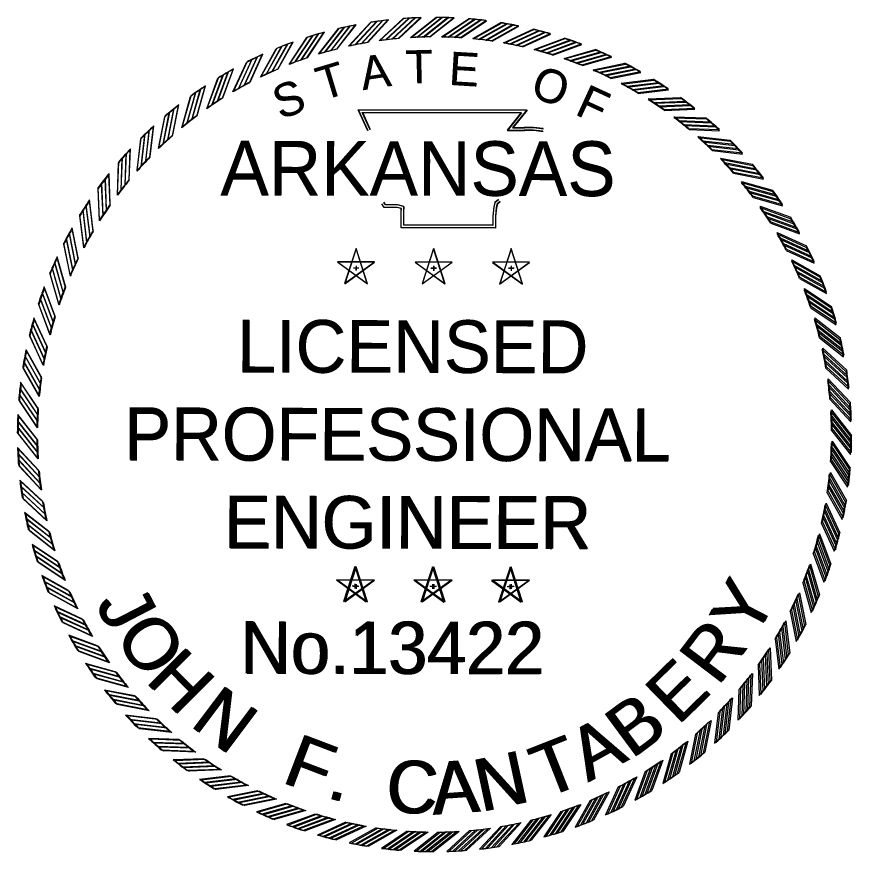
# Model space of a CAD drawing. Extents: x 0 to 38.1, y -1.4 to 22.
# Drawn here: x 35.582 to 38.013, y 15.407 to 17.836 of the extents above; entities that cross this region are included whole.
import ezdxf

# ---------------------------------------------------------------- set-up
doc = ezdxf.new("R2010")
doc.units = 0
doc.layers.add('Default', color=7, linetype='Continuous')

# ---------------------------------------------------------------- blocks, each defined once
blk = doc.blocks.new('STAR')
at = {"layer": 'Default'}
for p, q in [((-0.0001, 0.0615), (-0.0366, -0.0504)), ((0.0362, -0.0503), (0, 0.0617)), ((0.0587, 0.0188), (-0.059, 0.0189)), ((-0.0589, 0.0188), (0.0363, -0.0505)), ((-0.0365, -0.0503), (0.0589, 0.0188)), ((-0.0085, 0), (0.009, 0)), ((0, 0.0063), (0, -0.0085))]:
    blk.add_line(p, q, dxfattribs=at)
blk = doc.blocks.new('RP')
at = {"layer": 'Default'}
for p, q in [((-0.0781, 1.2656), (0.003, 1.33)), ((-0.058, 1.2667), (0.0216, 1.3299)), ((-0.0375, 1.2674), (0.0405, 1.3294)), ((-0.0176, 1.2679), (0.059, 1.3287))]:
    blk.add_line(p, q, dxfattribs=at)
for radius, start, end in [(1.33, 87.4562, 89.8699), (1.268, 90.7933, 93.5307)]:
    blk.add_arc((0, 0), radius, start, end, dxfattribs=at)

msp = doc.modelspace()

# ---------------------------------------------------------------- linework, layer by layer
at = {"layer": 'Default'}
for points in [[(36.6042, 17.5043), (36.5758, 17.5657), (37.0662, 17.566), (37.0253, 17.5145), (37.0586, 17.5149), (37.0864, 17.5153), (37.1142, 17.5122)], [(36.6051, 17.5046), (36.577, 17.5661), (37.0674, 17.5647), (37.0263, 17.5134), (37.0596, 17.5137), (37.0874, 17.514), (37.1152, 17.5108)], [(36.6112, 17.5076), (36.588, 17.5579), (37.0501, 17.5582), (37.009, 17.5065), (37.0587, 17.5071), (37.086, 17.5075), (37.1134, 17.5045)], [(36.6122, 17.5079), (36.5891, 17.5583), (37.0513, 17.557), (37.01, 17.5055), (37.0597, 17.5059), (37.087, 17.5062), (37.1143, 17.5031)], [(36.989, 17.2988), (36.9806, 17.292), (36.9778, 17.2818), (36.9751, 17.2564), (36.9751, 17.2225), (36.7013, 17.2225), (36.7013, 17.2682), (36.7013, 17.2784), (36.6902, 17.2818), (36.6512, 17.2818), (36.6443, 17.2924)], [(36.9892, 17.2978), (36.9808, 17.291), (36.978, 17.2809), (36.9752, 17.2554), (36.9751, 17.2215), (36.7013, 17.2225), (36.7014, 17.2682), (36.7015, 17.2784), (36.6904, 17.2818), (36.6514, 17.282), (36.6446, 17.2926)], [(36.9841, 17.3048), (36.9738, 17.2964), (36.9702, 17.2833), (36.9673, 17.2568), (36.9673, 17.2303), (36.7091, 17.2303), (36.7091, 17.2682), (36.7091, 17.2842), (36.6913, 17.2896), (36.6554, 17.2896), (36.6508, 17.2966)], [(36.9843, 17.3038), (36.974, 17.2955), (36.9704, 17.2823), (36.9674, 17.2559), (36.9673, 17.2293), (36.7091, 17.2302), (36.7092, 17.2682), (36.7093, 17.2841), (36.6916, 17.2896), (36.6557, 17.2897), (36.6511, 17.2968)]]:
    msp.add_lwpolyline(points, dxfattribs=at)

# ---------------------------------------------------------------- block references
for name, p, xscale, yscale, rotation in [('RP', (36.799, 16.6219), 0.9117655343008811, 0.9117655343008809, 9.000000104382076), ('RP', (36.7969, 16.6215), 0.9117655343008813, 0.9117655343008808, 8.804199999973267), ('RP', (36.799, 16.6219), 0.9117655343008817, 0.9117655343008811, 4.500000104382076), ('RP', (36.7969, 16.6215), 0.9117655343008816, 0.9117655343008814, 4.304199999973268), ('RP', (36.799, 16.6219), 0.9117655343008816, 0.911765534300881, 1.0438208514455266e-07), ('RP', (36.7969, 16.6215), 0.9117655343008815, 0.911765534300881, -0.19580000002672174), ('RP', (36.799, 16.6219), 0.9117655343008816, 0.911765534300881, -4.499999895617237), ('RP', (36.7969, 16.6215), 0.9117655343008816, 0.9117655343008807, -4.695800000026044), ('RP', (36.799, 16.6219), 0.9117655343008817, 0.9117655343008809, -8.999999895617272), ('RP', (36.7969, 16.6215), 0.9117655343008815, 0.911765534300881, -9.195800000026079), ('RP', (36.799, 16.6219), 0.9117655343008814, 0.9117655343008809, 13.500000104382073), ('RP', (36.7969, 16.6215), 0.9117655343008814, 0.9117655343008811, 13.304199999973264), ('RP', (36.799, 16.6219), 0.9117655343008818, 0.9117655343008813, -13.499999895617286), ('RP', (36.7969, 16.6215), 0.9117655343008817, 0.9117655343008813, -13.695800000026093), ('RP', (36.799, 16.6219), 0.9117655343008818, 0.911765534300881, -17.99999989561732), ('RP', (36.7969, 16.6215), 0.9117655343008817, 0.911765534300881, -18.19580000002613), ('RP', (36.799, 16.6219), 0.9117655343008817, 0.9117655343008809, 18.000000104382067), ('RP', (36.7969, 16.6215), 0.9117655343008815, 0.9117655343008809, 17.80419999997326), ('RP', (36.799, 16.6219), 0.9117655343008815, 0.911765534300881, 22.500000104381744), ('RP', (36.7969, 16.6215), 0.9117655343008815, 0.911765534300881, 22.304199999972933), ('RP', (36.799, 16.6219), 0.9117655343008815, 0.9117655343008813, -22.499999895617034), ('RP', (36.7969, 16.6215), 0.9117655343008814, 0.9117655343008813, -22.695800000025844), ('RP', (36.799, 16.6219), 0.9117655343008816, 0.9117655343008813, 27.000000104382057), ('RP', (36.7969, 16.6215), 0.9117655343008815, 0.9117655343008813, 26.80419999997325), ('RP', (36.799, 16.6219), 0.9117655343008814, 0.9117655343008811, -26.999999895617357), ('RP', (36.7969, 16.6215), 0.9117655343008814, 0.911765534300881, -27.19580000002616), ('RP', (36.799, 16.6219), 0.911765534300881, 0.9117655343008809, 31.500000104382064), ('RP', (36.7969, 16.6215), 0.9117655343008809, 0.9117655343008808, 31.30419999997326), ('RP', (36.799, 16.6219), 0.9117655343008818, 0.9117655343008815, -31.49999989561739), ('RP', (36.7969, 16.6215), 0.9117655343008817, 0.9117655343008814, -31.695800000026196), ('RP', (36.799, 16.6219), 0.9117655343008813, 0.911765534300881, 36.000000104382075), ('RP', (36.7969, 16.6215), 0.911765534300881, 0.9117655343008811, 35.804199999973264), ('RP', (36.799, 16.6219), 0.9117655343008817, 0.9117655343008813, -35.999999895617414), ('RP', (36.7969, 16.6215), 0.9117655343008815, 0.9117655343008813, -36.195800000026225), ('RP', (36.799, 16.6219), 0.9117655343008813, 0.911765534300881, 40.50000010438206), ('RP', (36.7969, 16.6215), 0.9117655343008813, 0.911765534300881, 40.30419999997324), ('RP', (36.799, 16.6219), 0.9117655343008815, 0.9117655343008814, -40.49999989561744), ('RP', (36.7969, 16.6215), 0.9117655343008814, 0.9117655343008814, -40.69580000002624), ('RP', (36.799, 16.6219), 0.9117655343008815, 0.911765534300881, -44.99999989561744), ('RP', (36.799, 16.6219), 0.9117655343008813, 0.9117655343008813, 45.00000010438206), ('RP', (36.7969, 16.6215), 0.9117655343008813, 0.911765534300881, 44.80419999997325), ('RP', (36.7969, 16.6215), 0.9117655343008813, 0.911765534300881, -45.19580000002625), ('RP', (36.799, 16.6219), 0.911765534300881, 0.9117655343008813, -49.499999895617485), ('RP', (36.7969, 16.6215), 0.911765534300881, 0.911765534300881, -49.69580000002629), ('RP', (36.799, 16.6219), 0.9117655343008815, 0.9117655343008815, 49.500000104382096), ('RP', (36.7969, 16.6215), 0.9117655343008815, 0.9117655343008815, 49.30419999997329), ('RP', (36.799, 16.6219), 0.9117655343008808, 0.9117655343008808, -53.999999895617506), ('RP', (36.7969, 16.6215), 0.9117655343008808, 0.9117655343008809, -54.1958000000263), ('RP', (36.799, 16.6219), 0.9117655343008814, 0.9117655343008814, 54.00000010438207), ('RP', (36.7969, 16.6215), 0.9117655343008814, 0.9117655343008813, 53.804199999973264), ('RP', (36.799, 16.6219), 0.911765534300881, 0.9117655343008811, -58.49999989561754), ('RP', (36.7969, 16.6215), 0.9117655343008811, 0.9117655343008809, -58.695800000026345), ('RP', (36.7969, 16.6215), 0.9117655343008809, 0.9117655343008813, 58.304199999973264), ('RP', (36.799, 16.6219), 0.911765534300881, 0.9117655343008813, 58.50000010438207), ('RP', (36.7969, 16.6215), 0.9117655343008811, 0.9117655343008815, 62.804199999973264), ('RP', (36.799, 16.6219), 0.9117655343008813, 0.9117655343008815, 63.000000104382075), ('RP', (36.7969, 16.6215), 0.9117655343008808, 0.9117655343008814, -63.19580000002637), ('RP', (36.799, 16.6219), 0.911765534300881, 0.9117655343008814, -62.99999989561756), ('RP', (36.7969, 16.6215), 0.911765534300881, 0.9117655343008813, 67.30419999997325), ('STAR', (36.5696, 17.1065), 0.9117655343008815, 0.911765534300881, -0.19580000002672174), ('STAR', (36.57, 17.106), 0.9117655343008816, 0.911765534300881, 1.0438208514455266e-07), ('STAR', (36.7952, 17.1057), 0.9117655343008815, 0.911765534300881, -0.19580000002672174), ('STAR', (36.7956, 17.106), 0.9117655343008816, 0.911765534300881, 1.0438208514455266e-07), ('STAR', (37.0207, 17.1049), 0.9117655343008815, 0.911765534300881, -0.19580000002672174), ('STAR', (37.0211, 17.106), 0.9117655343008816, 0.911765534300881, 1.0438208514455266e-07), ('RP', (36.7969, 16.6215), 0.9117655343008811, 0.9117655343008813, -67.69580000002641), ('RP', (36.799, 16.6219), 0.911765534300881, 0.9117655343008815, -67.49999989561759), ('RP', (36.799, 16.6219), 0.911765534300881, 0.9117655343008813, 67.50000010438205), ('RP', (36.7969, 16.6215), 0.9117655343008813, 0.9117655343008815, 71.80419999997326), ('RP', (36.799, 16.6219), 0.9117655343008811, 0.9117655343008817, 72.00000010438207), ('RP', (36.7969, 16.6215), 0.911765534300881, 0.9117655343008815, -72.19580000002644), ('RP', (36.799, 16.6219), 0.9117655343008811, 0.9117655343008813, -71.99999989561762), ('RP', (36.7969, 16.6215), 0.9117655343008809, 0.911765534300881, -76.69580000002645), ('RP', (36.799, 16.6219), 0.9117655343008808, 0.9117655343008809, -76.49999989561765), ('RP', (36.7969, 16.6215), 0.911765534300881, 0.9117655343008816, 76.30419999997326), ('RP', (36.799, 16.6219), 0.9117655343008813, 0.9117655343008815, 76.50000010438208), ('RP', (36.7969, 16.6215), 0.911765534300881, 0.9117655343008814, -81.19580000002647), ('RP', (36.799, 16.6219), 0.9117655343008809, 0.9117655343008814, -80.99999989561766), ('RP', (36.7969, 16.6215), 0.9117655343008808, 0.9117655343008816, 80.80419999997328), ('RP', (36.799, 16.6219), 0.9117655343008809, 0.9117655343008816, 81.0000001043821), ('RP', (36.7969, 16.6215), 0.9117655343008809, 0.9117655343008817, 85.30419999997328), ('RP', (36.7969, 16.6215), 0.9117655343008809, 0.9117655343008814, -85.69580000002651), ('RP', (36.799, 16.6219), 0.9117655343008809, 0.9117655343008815, -85.49999989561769), ('RP', (36.799, 16.6219), 0.9117655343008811, 0.9117655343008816, 85.50000010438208), ('RP', (36.7969, 16.6215), 0.911765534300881, 0.9117655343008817, 89.80419999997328), ('RP', (36.7969, 16.6215), 0.9117655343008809, 0.9117655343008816, -90.19580000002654), ('RP', (36.799, 16.6219), 0.911765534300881, 0.9117655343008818, -89.99999989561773), ('RP', (36.799, 16.6219), 0.9117655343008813, 0.9117655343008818, 90.0000001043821), ('RP', (36.7969, 16.6215), 0.911765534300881, 0.9117655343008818, 94.30419999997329), ('RP', (36.799, 16.6219), 0.9117655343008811, 0.9117655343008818, 94.5000001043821), ('RP', (36.7969, 16.6215), 0.911765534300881, 0.9117655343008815, -94.69580000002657), ('RP', (36.799, 16.6219), 0.9117655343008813, 0.9117655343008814, -94.49999989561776), ('RP', (36.7969, 16.6215), 0.911765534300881, 0.9117655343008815, -99.19580000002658), ('RP', (36.799, 16.6219), 0.9117655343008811, 0.9117655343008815, -98.99999989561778), ('RP', (36.7969, 16.6215), 0.9117655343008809, 0.9117655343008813, 98.8041999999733), ('RP', (36.799, 16.6219), 0.9117655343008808, 0.9117655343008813, 99.0000001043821), ('RP', (36.7969, 16.6215), 0.9117655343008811, 0.9117655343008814, -103.69580000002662), ('RP', (36.799, 16.6219), 0.911765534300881, 0.9117655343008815, -103.49999989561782), ('RP', (36.7969, 16.6215), 0.911765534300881, 0.9117655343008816, 103.30419999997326), ('RP', (36.799, 16.6219), 0.911765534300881, 0.9117655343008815, 103.50000010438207), ('RP', (36.7969, 16.6215), 0.9117655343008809, 0.9117655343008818, 107.80419999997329), ('RP', (36.799, 16.6219), 0.9117655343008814, 0.9117655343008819, 108.0000001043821), ('RP', (36.7969, 16.6215), 0.9117655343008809, 0.9117655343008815, -108.19580000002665), ('RP', (36.799, 16.6219), 0.9117655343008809, 0.9117655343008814, -107.99999989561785), ('RP', (36.7969, 16.6215), 0.9117655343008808, 0.9117655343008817, -112.69580000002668), ('RP', (36.799, 16.6219), 0.9117655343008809, 0.9117655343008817, -112.49999989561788), ('RP', (36.7969, 16.6215), 0.911765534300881, 0.9117655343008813, 112.30419999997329), ('RP', (36.799, 16.6219), 0.9117655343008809, 0.9117655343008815, 112.5000001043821), ('STAR', (36.5665, 16.1817), 0.9117655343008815, 0.911765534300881, -0.19580000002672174), ('STAR', (36.57, 16.1812), 0.9117655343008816, 0.911765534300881, 1.0438208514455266e-07), ('STAR', (36.792, 16.1809), 0.9117655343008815, 0.911765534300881, -0.19580000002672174), ('STAR', (36.7956, 16.1812), 0.9117655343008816, 0.911765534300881, 1.0438208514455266e-07), ('STAR', (37.0176, 16.1801), 0.9117655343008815, 0.911765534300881, -0.19580000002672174), ('STAR', (37.0211, 16.1812), 0.9117655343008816, 0.911765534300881, 1.0438208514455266e-07), ('RP', (36.7969, 16.6215), 0.9117655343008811, 0.9117655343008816, 116.80419999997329), ('RP', (36.799, 16.6219), 0.9117655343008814, 0.9117655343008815, 117.0000001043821), ('RP', (36.7969, 16.6215), 0.9117655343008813, 0.9117655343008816, -117.19580000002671), ('RP', (36.799, 16.6219), 0.9117655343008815, 0.9117655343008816, -116.9999998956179), ('RP', (36.7969, 16.6215), 0.9117655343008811, 0.9117655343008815, -121.69580000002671), ('RP', (36.799, 16.6219), 0.9117655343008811, 0.9117655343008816, -121.4999998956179), ('RP', (36.7969, 16.6215), 0.9117655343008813, 0.9117655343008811, 121.30419999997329), ('RP', (36.799, 16.6219), 0.9117655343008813, 0.9117655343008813, 121.5000001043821), ('RP', (36.7969, 16.6215), 0.9117655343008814, 0.9117655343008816, -126.19580000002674), ('RP', (36.799, 16.6219), 0.9117655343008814, 0.9117655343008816, -125.99999989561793), ('RP', (36.7969, 16.6215), 0.911765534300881, 0.911765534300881, 125.80419999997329), ('RP', (36.799, 16.6219), 0.911765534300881, 0.9117655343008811, 126.00000010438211), ('RP', (36.799, 16.6219), 0.9117655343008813, 0.9117655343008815, -130.49999989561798), ('RP', (36.7969, 16.6215), 0.9117655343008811, 0.9117655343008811, 130.3041999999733), ('RP', (36.799, 16.6219), 0.911765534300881, 0.9117655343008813, 130.50000010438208), ('RP', (36.7969, 16.6215), 0.9117655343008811, 0.9117655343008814, -130.6958000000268), ('RP', (36.7969, 16.6215), 0.9117655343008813, 0.911765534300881, -135.19580000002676), ('RP', (36.799, 16.6219), 0.9117655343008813, 0.9117655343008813, -134.99999989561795), ('RP', (36.7969, 16.6215), 0.9117655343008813, 0.911765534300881, 134.80419999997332), ('RP', (36.799, 16.6219), 0.9117655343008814, 0.9117655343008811, 135.00000010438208), ('RP', (36.7969, 16.6215), 0.9117655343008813, 0.9117655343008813, 139.30419999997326), ('RP', (36.799, 16.6219), 0.9117655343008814, 0.9117655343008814, 139.50000010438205), ('RP', (36.7969, 16.6215), 0.9117655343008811, 0.9117655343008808, -139.69580000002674), ('RP', (36.799, 16.6219), 0.911765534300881, 0.911765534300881, -139.49999989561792), ('RP', (36.799, 16.6219), 0.9117655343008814, 0.9117655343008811, -143.99999989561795), ('RP', (36.7969, 16.6215), 0.9117655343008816, 0.9117655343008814, 143.8041999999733), ('RP', (36.799, 16.6219), 0.9117655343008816, 0.9117655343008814, 144.00000010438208), ('RP', (36.7969, 16.6215), 0.9117655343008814, 0.9117655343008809, -144.19580000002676), ('RP', (36.7969, 16.6215), 0.9117655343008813, 0.9117655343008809, 148.3041999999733), ('RP', (36.799, 16.6219), 0.9117655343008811, 0.9117655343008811, 148.50000010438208), ('RP', (36.7969, 16.6215), 0.9117655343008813, 0.9117655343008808, -148.69580000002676), ('RP', (36.799, 16.6219), 0.911765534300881, 0.911765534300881, -148.49999989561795), ('RP', (36.7969, 16.6215), 0.9117655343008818, 0.9117655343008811, 152.8041999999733), ('RP', (36.799, 16.6219), 0.9117655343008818, 0.9117655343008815, 153.00000010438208), ('RP', (36.7969, 16.6215), 0.9117655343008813, 0.9117655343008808, -153.1958000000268), ('RP', (36.799, 16.6219), 0.9117655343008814, 0.9117655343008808, -152.99999989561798), ('RP', (36.799, 16.6219), 0.9117655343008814, 0.9117655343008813, -157.4999998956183), ('RP', (36.7969, 16.6215), 0.9117655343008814, 0.9117655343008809, 157.3041999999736), ('RP', (36.799, 16.6219), 0.9117655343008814, 0.911765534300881, 157.50000010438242), ('RP', (36.7969, 16.6215), 0.9117655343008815, 0.9117655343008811, -157.6958000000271), ('RP', (36.7969, 16.6215), 0.9117655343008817, 0.911765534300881, 161.8041999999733), ('RP', (36.799, 16.6219), 0.9117655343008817, 0.9117655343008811, 162.00000010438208), ('RP', (36.7969, 16.6215), 0.9117655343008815, 0.9117655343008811, -162.19580000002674), ('RP', (36.799, 16.6219), 0.9117655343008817, 0.911765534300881, -161.99999989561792), ('RP', (36.7969, 16.6215), 0.9117655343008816, 0.9117655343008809, 166.3041999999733), ('RP', (36.799, 16.6219), 0.9117655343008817, 0.9117655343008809, 166.50000010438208), ('RP', (36.7969, 16.6215), 0.9117655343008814, 0.9117655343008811, -166.69580000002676), ('RP', (36.799, 16.6219), 0.9117655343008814, 0.9117655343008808, -166.49999989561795), ('RP', (36.7969, 16.6215), 0.9117655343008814, 0.9117655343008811, 170.8041999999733), ('RP', (36.799, 16.6219), 0.9117655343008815, 0.911765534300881, 171.00000010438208), ('RP', (36.7969, 16.6215), 0.911765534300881, 0.911765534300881, -171.19580000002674), ('RP', (36.799, 16.6219), 0.9117655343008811, 0.9117655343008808, -170.99999989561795), ('RP', (36.7969, 16.6215), 0.9117655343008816, 0.911765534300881, 175.3041999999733), ('RP', (36.799, 16.6219), 0.9117655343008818, 0.911765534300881, 175.50000010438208), ('RP', (36.7969, 16.6215), 0.9117655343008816, 0.9117655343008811, 179.8041999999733), ('RP', (36.799, 16.6219), 0.9117655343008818, 0.9117655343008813, -179.99999989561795), ('RP', (36.7969, 16.6215), 0.9117655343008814, 0.911765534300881, -175.69580000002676), ('RP', (36.799, 16.6219), 0.9117655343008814, 0.9117655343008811, -175.49999989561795)]:
    msp.add_blockref(name, p, dxfattribs=dict(at, xscale=xscale, yscale=yscale, rotation=rotation))

# ---------------------------------------------------------------- texts
for s, height, rotation, p in [('A', 0.0967, 8.6788, (36.5892, 17.6224)), ('A', 0.0967, 8.483, (36.5906, 17.6227)), ('T', 0.0967, 1.4789, (36.7142, 17.6416)), ('T', 0.0967, 1.2831, (36.7156, 17.6416)), ('E', 0.0967, 356.672, (36.838, 17.6387)), ('E', 0.0967, 356.4762, (36.8394, 17.6382)), ('T', 0.0967, 16.9015, (36.4718, 17.5917)), ('T', 0.0967, 16.7057, (36.473, 17.5925)), ('O', 0.0967, 341.2218, (37.0728, 17.6055)), ('O', 0.0967, 341.026, (37.0741, 17.6042)), ('S', 0.0967, 19.5768, (36.3498, 17.5377)), ('S', 0.0967, 19.7726, (36.3488, 17.5365)), ('F', 0.0967, 335.3628, (37.2032, 17.5545)), ('F', 0.0967, 335.167, (37.2044, 17.5528)), ('ARKANSAS', 0.15788, 0, (36.1749, 17.3164)), ('ARKANSAS', 0.15788, 359.8042, (36.1753, 17.3182)), ('LICENSED', 0.15285, 359.8042, (36.2225, 16.8027)), ('LICENSED', 0.15285, 0, (36.224, 16.8011)), ('PROFESSIONAL', 0.152848, 359.8042, (35.8941, 16.5482)), ('PROFESSIONAL', 0.152848, 0, (35.8964, 16.5454)), ('ENGINEER', 0.15285, 359.8042, (36.1844, 16.2916)), ('ENGINEER', 0.15285, 0, (36.1876, 16.2898)), ('Y', 0.1528, 62.5392, (37.7287, 16.0217)), ('Y', 0.1528, 62.735, (37.7328, 16.0252)), ('J', 0.1528, 297.2813, (35.8089, 16.1303)), ('J', 0.1528, 297.4771, (35.8127, 16.1272)), ('O', 0.1528, 304.1899, (35.8631, 16.0365)), ('O', 0.1528, 304.3857, (35.8671, 16.0337)), ('No.13422', 0.15225, 359.8042, (36.2314, 15.9271)), ('No.13422', 0.15225, 0, (36.2358, 15.9255)), ('R', 0.1528, 52.7437, (37.622, 15.8871)), ('R', 0.1528, 52.9395, (37.6265, 15.8902)), ('H', 0.1528, 314.7447, (35.9532, 15.9048)), ('H', 0.1528, 314.9405, (35.9577, 15.9023)), ('E', 0.1528, 44.306, (37.5055, 15.7733)), ('E', 0.1528, 44.5018, (37.5105, 15.7761)), ('N', 0.1528, 322.9417, (36.0823, 15.777)), ('N', 0.1528, 323.1375, (36.0872, 15.7749)), ('B', 0.1528, 36.505, (37.3707, 15.676)), ('B', 0.1528, 36.7008, (37.3759, 15.6783)), ('A', 0.1528, 28.8562, (37.2437, 15.6093)), ('A', 0.1528, 29.052, (37.2492, 15.6112)), ('F', 0.1528, 339.0288, (36.3491, 15.6115)), ('F', 0.1528, 339.2246, (36.3546, 15.6103)), ('T', 0.1528, 21.4329, (37.1166, 15.5615)), ('T', 0.1528, 21.6287, (37.1223, 15.563)), ('N', 0.1528, 12.0703, (36.9322, 15.5234)), ('N', 0.1528, 12.2661, (36.938, 15.5242)), ('C', 0.1528, 356.1028, (36.6523, 15.5257)), ('C', 0.1528, 356.2986, (36.6581, 15.5256)), ('A', 0.1528, 3.9092, (36.7925, 15.5156)), ('A', 0.1528, 4.105, (36.7984, 15.5159)), ('.', 0.1528, 344.7037, (36.4795, 15.5663)), ('.', 0.1528, 344.8995, (36.4851, 15.5656))]:
    msp.add_text(s, height=height, rotation=rotation, dxfattribs=at).set_placement(p)

doc.saveas('drawing.dxf')
